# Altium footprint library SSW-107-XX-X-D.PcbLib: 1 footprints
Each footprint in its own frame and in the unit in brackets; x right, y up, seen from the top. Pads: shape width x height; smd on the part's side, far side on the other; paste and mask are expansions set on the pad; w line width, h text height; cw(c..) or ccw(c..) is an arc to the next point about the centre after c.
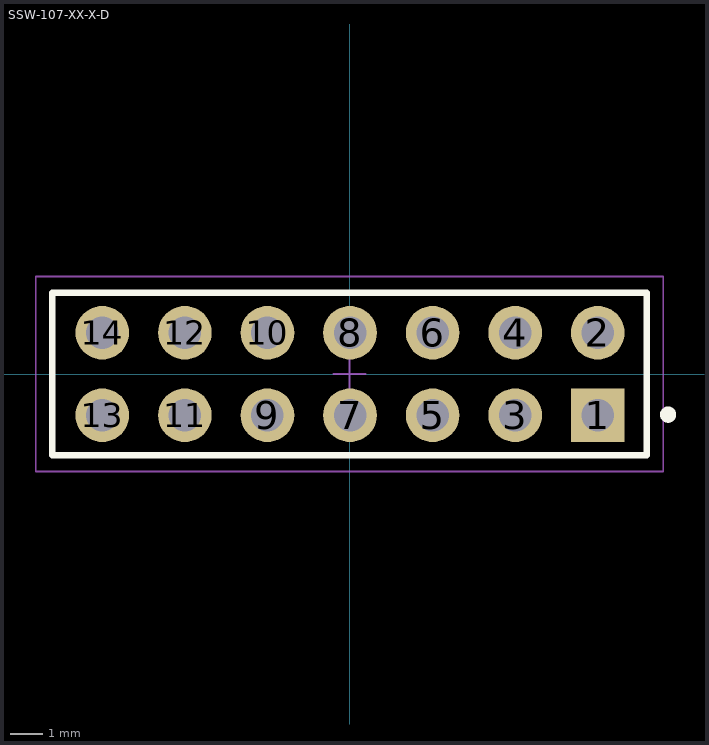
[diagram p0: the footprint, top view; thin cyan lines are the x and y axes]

## SSW-107-XX-X-D [mm] "2.54mm pitch, 14 pin, socket strip; double row"
height 8.51
pads (14):
  rect 1.65x1.65 / inner round 1.65 / far side rect 1.65x1.65 hole 1 mask+0: 1(7.635,-1.27)
  round 1.65 hole 1 mask+0: 2(7.635,1.27) 3(5.095,-1.27) 4(5.095,1.27) 5(2.555,-1.27) 6(2.555,1.27) 7(0.015,-1.27) 8(0.015,1.27) 9(-2.525,-1.27) 10(-2.525,1.27) 11(-5.065,-1.27) 12(-5.065,1.27) 13(-7.605,-1.27) 14(-7.605,1.27)
Top Overlay:
  circle w0.25: c9.8,-1.25 r0.125
  lines w0.2: -9.15,-2.5 -9.15,2.5 9.15,2.5 9.15,-2.5 -9.15,-2.5
Mechanical 12:
  lines w0.001: -9.15,-2.5 -9.15,2.5 9.15,2.5 9.15,-2.5 -9.15,-2.5
Mechanical 13:
  lines w0.1: -9.15,-2.5 -9.15,2.5 9.15,2.5 9.15,-2.5 -9.15,-2.5
  text ".Designator" at 0,-0.127 h1.52
Mechanical 15:
  lines w0.05: -0.5,0 0.5,0 ; 0,-0.5 0,0.5 ; -9.65,-3 -9.65,3 9.65,3 9.65,-3 -9.65,-3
